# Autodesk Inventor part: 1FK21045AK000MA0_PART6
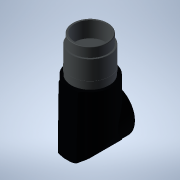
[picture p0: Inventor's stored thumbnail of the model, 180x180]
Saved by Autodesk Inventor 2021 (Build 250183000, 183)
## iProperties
Created: 2025-04
Part Number: 1FK21045AK000MA0_PART6
Material: Generic
Catalog Web Link: www.3dfindit.com
Description: -Servo synchronous motor
Document SubType Name: Modeling
Designer: psAdmin
Mass: 11.0817 g
Surface Area: 35.706 cm^2
Volume: 11.0817 cm^3
Density: 1 g/cm^3
Appearance: PSOLRGB-176-176-176
Category: PARTsolutions
Title: 1FK21045AK000MA0_PART6
Author: Cadenas PARTsolutions
Comments: Servo synchronous motor
Sending System: PARTsolutions
Preprocessor: ST-DEVELOPER v19.3
PSOL_IDENT_0: {$CADENAS_DATA/23d-libs/siemens_ag/_cat_/3d/2f/1fk21045ak000ma0.prj},213 {VTYP=3D},{NB=1FK21045AK000
PSOL_IDENT_1: MA0_PART6},{LINA=1FK21045AK000MA0_PART6},{NN=1FK21045AK000MA0_PART6},{NOPRJ=TRUE},{DATE=19.08.2025 1
PSOL_IDENT_2: 4:00:34},{GEOMDATE=30.07.2025 02:01:24},{VERSION=},{LINEID=10},{WBVAR=},{WBNUMERIC=}  {NB=1FK21045AK
PSOL_IDENT_3: 000MA0_PART6},{LINA=1FK21045AK000MA0_PART6},{KT=DUMMY},{PREVIEW=../../../_pool_/a9/69/p_d211_xx_0081
PSOL_IDENT_4: 8j.png},{DESCSHORT=SIMOTICS S-1FK2 HD, SINAMICS S210 3AC 400V-480V, 1.7 Nm, 6000 rpm},{DESCLONG=SIMO
PSOL_IDENT_5: TICS S-1FK2 HD servo motor M0=2.4 Nm; PN = 1.07 kW at nN=6000 rpm (380-480 V); PN = 0.75 kW at nN=30
PSOL_IDENT_6: 00 rpm (200-240 V); degree of protection IP64; cylindrical shaft D19x40mm; absolute encoder 22-bit +
PSOL_IDENT_7: 12-bit multiturn (encoder AM22DQC); with OCC interface; plug size M17, rotatable; SIMOTICS S-1FK2 s
PSOL_IDENT_8: ervomotorfor a wide range of uses in industrial environments. SIMOTICS S‑1FK2 servomotors are compac
PSOL_IDENT_9: t synchronous motors with a high dynamic performance that set themselves apart as a result of their
PSOL_IDENT_10: high power density, degree of protection and overload capability. The motors are available in two va
PSOL_IDENT_11: riants: as High Dynamic variant (highest dynamic performance as a result of the low intrinsic moment
PSOL_IDENT_12: of inertia for applications demanding a high dynamic performance with low moved masses) - and as Co
PSOL_IDENT_13: mpact variant (precise and stable closed-loop control for medium up to large moved masses as a resul
PSOL_IDENT_14: t of a medium intrinsic moment of inertia). SIMOTICSS‑1FK2 servomotors fully exploit their strengths
PSOL_IDENT_15: in a system with the SINAMICSS210 frequency converter and simple connection using the one cable con
PSOL_IDENT_16: nection (OCC). Advantages include the short control and positioning times, fast and precise correcti
PSOL_IDENT_17: on of disturbing quantities as well as stable control with a high dynamic performance. The servo mot
PSOL_IDENT_18: ors can be configured to address a wide range of requirements. For example with and without holding
PSOL_IDENT_19: brake, IP64 or IP65 degree of protection, singleturn or multiturn absolute encoders - to name just a
PSOL_IDENT_20: few. Further, the servomotors are available in different shaft heights extending from 20 to 100. A
PSOL_IDENT_21: shaft sealing ring is available to achieve an IP65 degree of protection and for subsequent mounting
PSOL_IDENT_22: at the motor or as spare part. SIMOTICS - the optimum motor for each and every motion control applic
PSOL_IDENT_23: ation.},{INTNO=804766789342},{SUPPLIERALTNO=1FK2104-5AK00-0MA0},{MANUID=1FK21045AK000MA0},{MANUNAME=
PSOL_IDENT_24: Siemens},{MANUTYPEDESC=Synchronous motor 1FK2-HD 2,39 Nm},{AAU732=SIMOTICS},{AAO057=S-1FK2},{AAU734=
PSOL_IDENT_25: SIMOTICS S-1FK2 HD servo motor M0=2.4 Nm; PN = 1.07 kW at nN=6000 rpm (380-480 V); PN = 0.75 kW at n
PSOL_IDENT_26: N=3000 rpm (200-240 V); degree of protection IP64; cylindrical shaft D19x40mm; absolute encoder 22-b
PSOL_IDENT_27: it + 12-bit multiturn (encoder AM22DQC); with OCC interface; plug size M17, rotatable;},{AAW338=Sync
PSOL_IDENT_28: hronous motor 1FK2-HD 2,39 Nm},{AAO742=SIMOTICS},{AAO663=4042948691151},{NOCUPEROU=1},{PRICEQUANTITY=
PSOL_IDENT_29: 1},{QUANTITYMIN=1},{QUANTITYINT=1},{CTN=85015100},{COO=DE},{AAO676=1FK2104-5AK00-0MA0},{AAO677=Sieme
PSOL_IDENT_30: ns AG},{ORDERUNIT=C62},{CONTENTUNIT=C62}
NB: 1FK21045AK000MA0_PART6
NT: Servo synchronous motor
NBSYN: $MANUID._PART6
LINA: 1FK21045AK000MA0_PART6
CATALOG: SIEMENS
PREVIEW: ../../../_pool_/a9/69/p_d211_xx_00818j.png
DESCSHORT: SIMOTICS S-1FK2 HD, SINAMICS S210 3AC 400V-480V, 1.7 Nm, 6000 rpm
DESCLONG: SIMOTICS S-1FK2 HD servo motor M0=2.4 Nm; PN = 1.07 kW at nN=6000 rpm (380-480 V); PN = 0.75 kW at nN=3000 rpm (200-240 V); degree of protection IP64; cylindric
INTNO: 804766789342
SUPPLIERALTNO: 1FK2104-5AK00-0MA0
MANUID: 1FK21045AK000MA0
MANUNAME: Siemens
MANUTYPEDESC: Synchronous motor 1FK2-HD 2,39 Nm
AAU732: SIMOTICS
AAO057: S-1FK2
AAU734: SIMOTICS S-1FK2 HD servo motor M0=2.4 Nm; PN = 1.07 kW at nN=6000 rpm (380-480 V); PN = 0.75 kW at nN=3000 rpm (200-240 V); degree of protection IP64; cylindric
AAW338: Synchronous motor 1FK2-HD 2,39 Nm
AAO742: SIMOTICS
AAO663: 4042948691151.0
NOCUPEROU: 1
PRICEQUANTITY: 1
QUANTITYMIN: 1
QUANTITYINT: 1
CTN: 85015100
COO: DE
ARTICLENO: 1FK21045AK000MA0_PART6
BOMINFO: 1FK21045AK000MA0_PART6
CREATOR: CADENAS GmbH
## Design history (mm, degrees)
feature "2025_04_17_15_39_51_0697"
body "Solid1"
